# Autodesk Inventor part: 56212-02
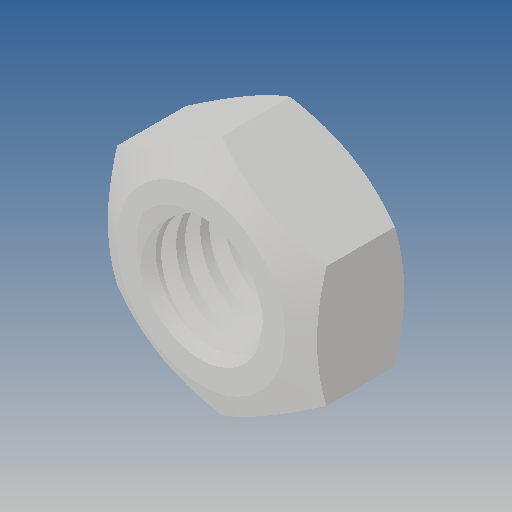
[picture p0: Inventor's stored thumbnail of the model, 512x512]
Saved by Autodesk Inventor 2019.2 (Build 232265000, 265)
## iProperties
Created: 2011-12
Part Number: 56212-02
Material: Ogólny
Document SubType Name: Modeling
Designer: CADENGINEERING4
Density: 1 g/cm^3
Appearance: Domyślna
Author: CADENGINEERING4
Revision Number: ÈÎºÎ
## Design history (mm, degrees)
feature "¾µÏò1"
node "Bryła1"
